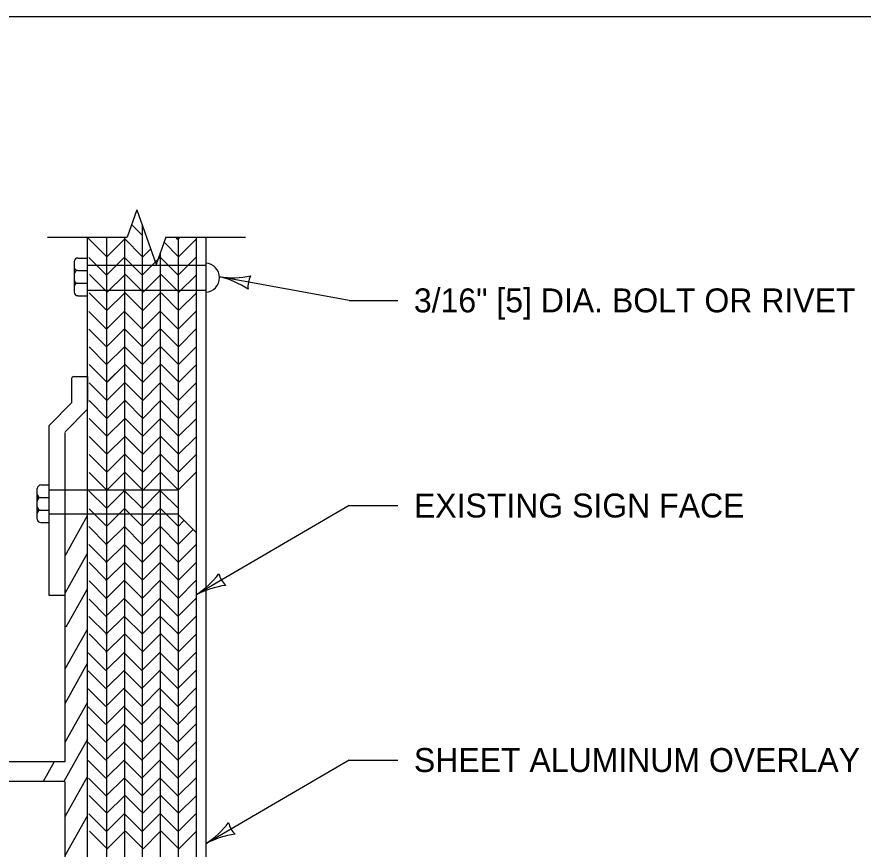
# Model space of a CAD drawing. Extents: x 49991.4 to 50021, y 49987.6 to 50011.4.
# Drawn here: x 50002.065 to 50004.187, y 50009.177 to 50011.263 of the extents above; entities that cross this region are included whole.
import ezdxf

# ---------------------------------------------------------------- set-up
doc = ezdxf.new("R2010")
doc.units = 0
for name, color, linetype in [('Level 1', 7, 'Continuous'), ('Level 2', 7, 'Continuous'), ('Level 3', 7, 'Continuous'), ('Level 4', 7, 'Continuous'), ('Level 6', 7, 'Continuous')]:
    doc.layers.add(name, color=color, linetype=linetype)

msp = doc.modelspace()

# ---------------------------------------------------------------- linework, layer by layer
at = {"layer": 'Level 1'}
for p, q in [((50002.3796, 50010.7159), (50002.3529, 50010.7426)), ((50002.3796, 50010.7406), (50002.3796, 50008.4555)), ((50002.2906, 50010.6615), (50002.2416, 50010.7107)), ((50002.2416, 50010.7107), (50002.2416, 50008.1584)), ((50002.2896, 50010.7107), (50002.2896, 50008.1584)), ((50002.3346, 50010.7055), (50002.2906, 50010.6615)), ((50002.3346, 50010.7107), (50002.3346, 50008.1584)), ((50002.3796, 50010.6625), (50002.3346, 50010.7075)), ((50002.4691, 50010.705), (50002.4634, 50010.7107)), ((50002.4748, 50010.7107), (50002.4691, 50010.705)), ((50002.4696, 50010.7107), (50002.4696, 50008.1584)), ((50002.5146, 50010.7055), (50002.4706, 50010.6615)), ((50002.5146, 50010.7107), (50002.5146, 50008.1584)), ((50002.5387, 50010.7107), (50002.5387, 50008.1584)), ((50002.4706, 50010.6615), (50002.4343, 50010.6979)), ((50002.4006, 50010.6815), (50002.3806, 50010.6615)), ((50002.4246, 50010.6707), (50002.4246, 50008.1183)), ((50002.2088, 50010.6496), (50002.2088, 50010.5728)), ((50002.2181, 50010.6584), (50002.2416, 50010.6584)), ((50002.2896, 50010.6155), (50002.2453, 50010.66)), ((50002.3346, 50010.6605), (50002.2896, 50010.6155)), ((50002.3796, 50010.6155), (50002.3353, 50010.66)), ((50002.4246, 50010.6605), (50002.3796, 50010.6155)), ((50002.4696, 50010.6155), (50002.4253, 50010.66)), ((50002.5146, 50010.6605), (50002.4696, 50010.6155)), ((50002.2181, 50010.6269), (50002.2416, 50010.6269)), ((50002.2915, 50010.5724), (50002.2472, 50010.6168)), ((50002.3346, 50010.6155), (50002.2915, 50010.5724)), ((50002.3815, 50010.5724), (50002.3372, 50010.6168)), ((50002.4246, 50010.6155), (50002.3815, 50010.5724)), ((50002.4715, 50010.5724), (50002.4272, 50010.6168)), ((50002.5146, 50010.6155), (50002.4715, 50010.5724)), ((50002.2088, 50010.5955), (50002.2416, 50010.5955)), ((50002.2177, 50010.564), (50002.2416, 50010.564)), ((50002.2908, 50010.5268), (50002.2465, 50010.571)), ((50002.3346, 50010.5705), (50002.2908, 50010.5268)), ((50002.3808, 50010.5268), (50002.3365, 50010.571)), ((50002.4246, 50010.5705), (50002.3808, 50010.5268)), ((50002.4708, 50010.5268), (50002.4265, 50010.571)), ((50002.5146, 50010.5705), (50002.4708, 50010.5268)), ((50002.2895, 50010.4804), (50002.2452, 50010.5246)), ((50002.3346, 50010.5255), (50002.2895, 50010.4804)), ((50002.3795, 50010.4804), (50002.3352, 50010.5246)), ((50002.4246, 50010.5255), (50002.3795, 50010.4804)), ((50002.4695, 50010.4804), (50002.4252, 50010.5246)), ((50002.5146, 50010.5255), (50002.4695, 50010.4804)), ((50002.2901, 50010.436), (50002.2458, 50010.4803)), ((50002.3346, 50010.4805), (50002.2901, 50010.436)), ((50002.3801, 50010.436), (50002.3358, 50010.4803)), ((50002.4246, 50010.4805), (50002.3801, 50010.436)), ((50002.4701, 50010.436), (50002.4258, 50010.4803)), ((50002.5146, 50010.4805), (50002.4701, 50010.436)), ((50002.2902, 50010.3911), (50002.246, 50010.4354)), ((50002.3346, 50010.4355), (50002.2902, 50010.3911)), ((50002.3802, 50010.3911), (50002.336, 50010.4354)), ((50002.4246, 50010.4355), (50002.3802, 50010.3911)), ((50002.4702, 50010.3911), (50002.426, 50010.4354)), ((50002.5146, 50010.4355), (50002.4702, 50010.3911)), ((50002.291, 50010.3469), (50002.2467, 50010.3911)), ((50002.3346, 50010.3905), (50002.2906, 50010.3465)), ((50002.3346, 50010.3905), (50002.291, 50010.3469)), ((50002.381, 50010.3469), (50002.3367, 50010.3911)), ((50002.4246, 50010.3905), (50002.381, 50010.3469)), ((50002.471, 50010.3469), (50002.4267, 50010.3911)), ((50002.5146, 50010.3905), (50002.4706, 50010.3465)), ((50002.5146, 50010.3905), (50002.471, 50010.3469)), ((50002.2025, 50010.2963), (50002.2025, 50010.3566)), ((50002.2068, 50010.3611), (50002.2426, 50010.3611)), ((50002.2426, 50010.2963), (50002.2426, 50010.3611)), ((50002.2906, 50010.3015), (50002.2463, 50010.3459)), ((50002.3346, 50010.3455), (50002.2906, 50010.3015)), ((50002.3806, 50010.3015), (50002.3363, 50010.3459)), ((50002.4246, 50010.3455), (50002.3806, 50010.3015)), ((50002.4706, 50010.3015), (50002.4263, 50010.3459)), ((50002.5146, 50010.3455), (50002.4706, 50010.3015)), ((50002.2025, 50010.2963), (50002.1461, 50010.2388)), ((50002.2906, 50010.2565), (50002.2463, 50010.3009)), ((50002.3346, 50010.3005), (50002.2906, 50010.2565)), ((50002.3806, 50010.2565), (50002.3363, 50010.3009)), ((50002.4246, 50010.3005), (50002.3806, 50010.2565)), ((50002.4706, 50010.2565), (50002.4263, 50010.3009)), ((50002.5146, 50010.3005), (50002.4706, 50010.2565)), ((50002.2416, 50010.2789), (50002.1862, 50010.2224)), ((50002.1461, 50009.8125), (50002.1461, 50010.2388)), ((50002.2906, 50010.2115), (50002.2463, 50010.2559)), ((50002.3346, 50010.2555), (50002.2906, 50010.2115)), ((50002.3806, 50010.2115), (50002.3363, 50010.2559)), ((50002.4246, 50010.2555), (50002.3806, 50010.2115)), ((50002.4706, 50010.2115), (50002.4263, 50010.2559)), ((50002.5146, 50010.2555), (50002.4706, 50010.2115)), ((50002.1852, 50010.2214), (50002.1852, 50009.3955)), ((50002.2906, 50010.1665), (50002.2463, 50010.2109)), ((50002.3346, 50010.2105), (50002.2906, 50010.1665)), ((50002.3806, 50010.1665), (50002.3363, 50010.2109)), ((50002.4246, 50010.2105), (50002.3806, 50010.1665)), ((50002.4706, 50010.1665), (50002.4263, 50010.2109)), ((50002.5146, 50010.2105), (50002.4706, 50010.1665)), ((50002.2906, 50010.1215), (50002.2463, 50010.1659)), ((50002.3346, 50010.1655), (50002.2906, 50010.1215)), ((50002.3806, 50010.1215), (50002.3363, 50010.1659)), ((50002.4246, 50010.1655), (50002.3806, 50010.1215)), ((50002.4706, 50010.1215), (50002.4263, 50010.1659)), ((50002.5146, 50010.1655), (50002.4706, 50010.1215)), ((50002.2906, 50010.0765), (50002.2463, 50010.1209)), ((50002.3346, 50010.1205), (50002.2906, 50010.0765)), ((50002.3806, 50010.0765), (50002.3363, 50010.1209)), ((50002.4246, 50010.1205), (50002.3806, 50010.0765)), ((50002.4706, 50010.0765), (50002.4263, 50010.1209)), ((50002.1162, 50010.0039), (50002.1162, 50010.0808)), ((50002.125, 50010.0895), (50002.1461, 50010.0895)), ((50002.1852, 50010.0769), (50002.2416, 50010.0769)), ((50002.2895, 50010.0309), (50002.2452, 50010.0751)), ((50002.3346, 50010.0755), (50002.2906, 50010.0315)), ((50002.3795, 50010.0309), (50002.3352, 50010.0751)), ((50002.4246, 50010.0755), (50002.3806, 50010.0315)), ((50002.4695, 50010.0309), (50002.4252, 50010.0751)), ((50002.1162, 50010.058), (50002.1462, 50010.058)), ((50002.1162, 50010.0266), (50002.1462, 50010.0266)), ((50002.2896, 50009.986), (50002.246, 50010.0296)), ((50002.3346, 50010.0305), (50002.2896, 50009.9855)), ((50002.3796, 50009.986), (50002.336, 50010.0296)), ((50002.4246, 50010.0305), (50002.3796, 50009.9855)), ((50002.4696, 50009.986), (50002.426, 50010.0296)), ((50002.1852, 50010.017), (50002.2416, 50010.017)), ((50002.2416, 50010.0119), (50002.1852, 50009.911)), ((50002.1247, 50009.9951), (50002.1462, 50009.9951)), ((50002.2895, 50009.9405), (50002.2452, 50009.985)), ((50002.3346, 50009.9855), (50002.2885, 50009.9394)), ((50002.3795, 50009.9405), (50002.3352, 50009.985)), ((50002.4246, 50009.9855), (50002.3785, 50009.9394)), ((50002.4695, 50009.9405), (50002.4252, 50009.985)), ((50002.4841, 50010), (50002.4696, 50009.9855)), ((50002.507, 50009.9779), (50002.4685, 50009.9394)), ((50002.2895, 50009.8959), (50002.2452, 50009.9401)), ((50002.3346, 50009.9405), (50002.2885, 50009.8944)), ((50002.3795, 50009.8959), (50002.3352, 50009.9401)), ((50002.4246, 50009.9405), (50002.3785, 50009.8944)), ((50002.4695, 50009.8959), (50002.4252, 50009.9401)), ((50002.5146, 50009.9405), (50002.4685, 50009.8944)), ((50002.2401, 50009.9159), (50002.1852, 50009.8178)), ((50002.2902, 50009.851), (50002.246, 50009.8953)), ((50002.3346, 50009.8955), (50002.2885, 50009.8494)), ((50002.3802, 50009.851), (50002.336, 50009.8953)), ((50002.4246, 50009.8955), (50002.3785, 50009.8494)), ((50002.4702, 50009.851), (50002.426, 50009.8953)), ((50002.5146, 50009.8955), (50002.4685, 50009.8494)), ((50002.2902, 50009.8046), (50002.246, 50009.849)), ((50002.3346, 50009.8505), (50002.2885, 50009.8044)), ((50002.3802, 50009.8046), (50002.336, 50009.849)), ((50002.4246, 50009.8505), (50002.3785, 50009.8044)), ((50002.4702, 50009.8046), (50002.426, 50009.849)), ((50002.5146, 50009.8505), (50002.4685, 50009.8044)), ((50002.2402, 50009.8263), (50002.1879, 50009.733)), ((50002.1852, 50009.8125), (50002.1461, 50009.8125)), ((50002.2902, 50009.7593), (50002.246, 50009.8035)), ((50002.3346, 50009.8055), (50002.2885, 50009.7594)), ((50002.3802, 50009.7593), (50002.336, 50009.8035)), ((50002.4246, 50009.8055), (50002.3785, 50009.7594)), ((50002.4702, 50009.7593), (50002.426, 50009.8035)), ((50002.5146, 50009.8055), (50002.4685, 50009.7594)), ((50002.2895, 50009.7159), (50002.2452, 50009.7601)), ((50002.3346, 50009.7605), (50002.2885, 50009.7144)), ((50002.3795, 50009.7159), (50002.3352, 50009.7601)), ((50002.4246, 50009.7605), (50002.3785, 50009.7144)), ((50002.4695, 50009.7159), (50002.4252, 50009.7601)), ((50002.5146, 50009.7605), (50002.4685, 50009.7144)), ((50002.2402, 50009.7258), (50002.1852, 50009.6276)), ((50002.2902, 50009.6718), (50002.246, 50009.716)), ((50002.3346, 50009.7155), (50002.2885, 50009.6694)), ((50002.3802, 50009.6718), (50002.336, 50009.716)), ((50002.4246, 50009.7155), (50002.3785, 50009.6694)), ((50002.4702, 50009.6718), (50002.426, 50009.716)), ((50002.5146, 50009.7155), (50002.4685, 50009.6694)), ((50002.2885, 50009.6244), (50002.2442, 50009.6686)), ((50002.3346, 50009.6705), (50002.2885, 50009.6244)), ((50002.3785, 50009.6244), (50002.3342, 50009.6686)), ((50002.4246, 50009.6705), (50002.3785, 50009.6244)), ((50002.4685, 50009.6244), (50002.4242, 50009.6686)), ((50002.5146, 50009.6705), (50002.4685, 50009.6244)), ((50002.2416, 50009.6418), (50002.1852, 50009.541)), ((50002.2885, 50009.5794), (50002.2442, 50009.6236)), ((50002.3346, 50009.6255), (50002.2885, 50009.5794)), ((50002.3785, 50009.5794), (50002.3342, 50009.6236)), ((50002.4246, 50009.6255), (50002.3785, 50009.5794)), ((50002.4685, 50009.5794), (50002.4242, 50009.6236)), ((50002.5146, 50009.6255), (50002.4685, 50009.5794)), ((50002.3346, 50009.5805), (50002.2885, 50009.5344)), ((50002.4246, 50009.5805), (50002.3785, 50009.5344)), ((50002.5146, 50009.5805), (50002.4685, 50009.5344)), ((50002.2885, 50009.5344), (50002.2442, 50009.5786)), ((50002.3785, 50009.5344), (50002.3342, 50009.5786)), ((50002.4685, 50009.5344), (50002.4242, 50009.5786)), ((50002.2412, 50009.5436), (50002.1852, 50009.4435)), ((50002.2885, 50009.4894), (50002.2442, 50009.5336)), ((50002.3346, 50009.5355), (50002.2885, 50009.4894)), ((50002.3785, 50009.4894), (50002.3342, 50009.5336)), ((50002.4246, 50009.5355), (50002.3785, 50009.4894)), ((50002.4685, 50009.4894), (50002.4242, 50009.5336)), ((50002.5146, 50009.5355), (50002.4685, 50009.4894)), ((50002.2885, 50009.4444), (50002.2442, 50009.4886)), ((50002.3346, 50009.4905), (50002.2885, 50009.4444)), ((50002.3785, 50009.4444), (50002.3342, 50009.4886)), ((50002.4246, 50009.4905), (50002.3785, 50009.4444)), ((50002.4685, 50009.4444), (50002.4242, 50009.4886)), ((50002.5146, 50009.4905), (50002.4685, 50009.4444)), ((50002.2416, 50009.4506), (50002.1831, 50009.3461)), ((50002.2885, 50009.3994), (50002.2442, 50009.4436)), ((50002.3346, 50009.4455), (50002.2885, 50009.3994)), ((50002.3785, 50009.3994), (50002.3342, 50009.4436)), ((50002.4246, 50009.4455), (50002.3785, 50009.3994)), ((50002.4685, 50009.3994), (50002.4242, 50009.4436)), ((50002.5146, 50009.4455), (50002.4685, 50009.3994)), ((50002.1852, 50009.3955), (50001.9436, 50009.3955)), ((50002.1588, 50009.3955), (50002.1311, 50009.3461)), ((50002.2885, 50009.3544), (50002.2442, 50009.3986)), ((50002.3346, 50009.4005), (50002.2885, 50009.3544)), ((50002.3785, 50009.3544), (50002.3342, 50009.3986)), ((50002.4246, 50009.4005), (50002.3785, 50009.3544)), ((50002.4685, 50009.3544), (50002.4242, 50009.3986)), ((50002.5146, 50009.4005), (50002.4685, 50009.3544)), ((50002.2407, 50009.3565), (50002.1852, 50009.2574)), ((50002.2891, 50009.31), (50002.2446, 50009.3543)), ((50002.3346, 50009.3555), (50002.2891, 50009.31)), ((50002.3791, 50009.31), (50002.3346, 50009.3543)), ((50002.4246, 50009.3555), (50002.3791, 50009.31)), ((50002.4691, 50009.31), (50002.4246, 50009.3543)), ((50002.5146, 50009.3555), (50002.4691, 50009.31)), ((50002.1852, 50009.3461), (50001.9436, 50009.3461)), ((50002.1852, 50009.3461), (50002.1852, 50008.5249)), ((50002.2906, 50009.2665), (50002.2463, 50009.3109)), ((50002.3346, 50009.3105), (50002.2906, 50009.2665)), ((50002.3806, 50009.2665), (50002.3363, 50009.3109)), ((50002.4246, 50009.3105), (50002.3806, 50009.2665)), ((50002.4706, 50009.2665), (50002.4263, 50009.3109)), ((50002.5146, 50009.3105), (50002.4706, 50009.2665)), ((50002.2896, 50009.2205), (50002.2453, 50009.265)), ((50002.3346, 50009.2655), (50002.2896, 50009.2205)), ((50002.3796, 50009.2205), (50002.3353, 50009.265)), ((50002.4246, 50009.2655), (50002.3796, 50009.2205)), ((50002.4696, 50009.2205), (50002.4253, 50009.265)), ((50002.5146, 50009.2655), (50002.4696, 50009.2205)), ((50002.2409, 50009.2595), (50002.1852, 50009.1598)), ((50002.2915, 50009.1774), (50002.2472, 50009.2217)), ((50002.3346, 50009.2205), (50002.2915, 50009.1774)), ((50002.3815, 50009.1774), (50002.3372, 50009.2217)), ((50002.4246, 50009.2205), (50002.3815, 50009.1774)), ((50002.4715, 50009.1774), (50002.4272, 50009.2217)), ((50002.5146, 50009.2205), (50002.4715, 50009.1774))]:
    msp.add_line(p, q, dxfattribs=at)
msp.add_lwpolyline([(50008.6146, 50011.2628), (50000.3356, 50011.2628), (50000.3356, 50000.0624), (50008.6146, 50000.0624)], close=True, dxfattribs=at)
for centre, radius, start, end in [((50002.2179, 50010.6494), 0.00905, 88.4176, 178.4176), ((50002.5372, 50010.609), 0.0363, 272.3294, 87.6706), ((50002.2179, 50010.636), 0.00908, 181.4043, 271.4043), ((50002.2177, 50010.6181), 0.00886, 93.9715, 179.6763), ((50002.2178, 50010.6045), 0.00904, 181.7251, 266.5357), ((50002.2177, 50010.5866), 0.00886, 90.2866, 179.7134), ((50002.2177, 50010.5729), 0.00885, 180.3237, 270.3237), ((50002.2068, 50010.3567), 0.00439, 90, 180), ((50002.1253, 50010.0804), 0.00909, 92.0412, 177.9588), ((50002.1247, 50010.0668), 0.00883, 194.4705, 269.7144), ((50002.125, 50010.0492), 0.00885, 96.3266, 179.772), ((50002.125, 50010.0354), 0.00884, 180.3026, 267.4326), ((50002.1248, 50010.018), 0.00863, 91.2206, 181.2206), ((50002.1249, 50010.0038), 0.00866, 178.9781, 268.9781)]:
    msp.add_arc(centre, radius, start, end, dxfattribs=at)
at = {"layer": 'Level 3'}
for p, q in [((50002.8988, 50010.5522), (50002.5735, 50010.6112)), ((50002.8988, 50010.5522), (50003.0208, 50010.5522)), ((50002.8988, 50010.0379), (50002.5146, 50009.8141)), ((50002.8988, 50010.0379), (50003.0208, 50010.0379)), ((50002.8988, 50009.3999), (50002.5387, 50009.1901)), ((50002.8988, 50009.3999), (50003.0208, 50009.3999))]:
    msp.add_line(p, q, dxfattribs=at)
for centre, radius, start, end in [((50002.6058, 50010.8419), 0.233, 262.0195, 281.2693), ((50002.5228, 50010.3947), 0.2223, 56.6482, 76.8317), ((50002.6994, 50010.5872), 0.0548, 151.331, 187.0533), ((50002.3875, 50010.0094), 0.233, 303.0485, 322.2983), ((50002.6254, 50009.8786), 0.0548, 192.36, 228.0824), ((50002.6185, 50009.6175), 0.2223, 97.6772, 117.8607), ((50002.4116, 50009.3854), 0.233, 303.0531, 322.3029), ((50002.6495, 50009.2546), 0.0548, 192.3646, 228.0869), ((50002.6426, 50008.9936), 0.2223, 97.6818, 117.8653)]:
    msp.add_arc(centre, radius, start, end, dxfattribs=at)
at = {"layer": 'Level 4'}
for p, q in [((50002.2417, 50010.6408), (50002.5387, 50010.6408)), ((50002.2426, 50010.5775), (50002.5387, 50010.5775)), ((50002.5143, 50010.1216), (50002.4703, 50010.0776)), ((50002.1461, 50010.0769), (50002.1852, 50010.0769)), ((50002.2416, 50010.0769), (50002.4691, 50010.0769)), ((50002.1461, 50010.017), (50002.1852, 50010.017)), ((50002.2416, 50010.017), (50002.4686, 50010.017)), ((50002.5146, 50009.9704), (50002.4688, 50010.0164))]:
    msp.add_line(p, q, dxfattribs=at)
at = {"layer": 'Level 6'}
for p, q in [((50002.3659, 50010.7792), (50002.3416, 50010.7107)), ((50002.3659, 50010.7792), (50002.3902, 50010.7107)), ((50002.1416, 50010.7107), (50002.3416, 50010.7107)), ((50002.3902, 50010.7107), (50002.4145, 50010.6422)), ((50002.4388, 50010.7107), (50002.4145, 50010.6422)), ((50002.4388, 50010.7107), (50002.6387, 50010.7107))]:
    msp.add_line(p, q, dxfattribs=at)

# ---------------------------------------------------------------- texts
at = {"layer": 'Level 2'}
for s, p in [('3/16" [5] DIA. BOLT OR RIVET', (50003.0608, 50010.5222)), ('EXISTING SIGN FACE', (50003.0608, 50010.0079)), ('SHEET ALUMINUM OVERLAY', (50003.0608, 50009.3699))]:
    msp.add_text(s, height=0.06, dxfattribs=at).set_placement(p)

doc.saveas('drawing.dxf')
